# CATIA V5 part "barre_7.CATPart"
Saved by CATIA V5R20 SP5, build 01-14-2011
Part number: barre_7
Bounding box of the stored display mesh (mm): x 6 to 18, y -140.227 to 17.773, z 171.5 to 181.5
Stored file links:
  M:\EU_thinkMotion\IAO_2010\iao\IAO_MMS_Groupe2\IAO_MMS_Groupe2\sdubois\sdubois\sdubois\IAO_mecanisme\barre_7.CATPart
  M:\EU_thinkMotion\IAO_2010\iao\IAO_MMS_Groupe2\IAO_MMS_Groupe2\sdubois\sdubois\sdubois\IAO_mecanisme\assembage final.CATProduct
  M:\EU_thinkMotion\IAO_2010\iao\IAO_MMS_Groupe2\IAO_MMS_Groupe2\sdubois\sdubois\sdubois\IAO_mecanisme\squelette_7.CATPart
  M:\EU_thinkMotion\IAO_2010\iao\IAO_MMS_Groupe2\IAO_MMS_Groupe2\sdubois\sdubois\sdubois\IAO_mecanisme\bati_0.CATPart
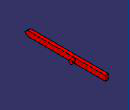
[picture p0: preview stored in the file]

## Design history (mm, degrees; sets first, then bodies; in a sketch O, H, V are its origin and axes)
External parameters (linked from other documents)
  External.largeur_barre_7 = 6 mm
  `External.diamètre trou oblong 'm'` = 8 mm
Set1
  Plane1 to Plane4: linked copy from another document
  Point1 to Point4: linked copy from another document
  DatumSurface1: linked copy from another document
Set2
  Point5: type Center, Curve edge [face of Pad2 from Sketch2.A1 | end face of Pad2]
Body1 (main body)
  Sketch1 on Plane1, origin (12, 0, 0), H (0, 1, 0), V (0, 0, 1)
    line L1 (-134.2269, 181.5) -> (17.7731, 181.5)
    point P1 (-134.2269, 181.5)
    point P2 (17.7731, 181.5)
    line L2 (-134.2269, 171.5) -> (17.7731, 171.5)
    point P3 (-134.2269, 171.5)
    point P4 (17.7731, 171.5)
    line L3 (-134.2269, 181.5) -> (-140.2269, 176.5)
    point P5 (-134.2269, 181.5)
    point P6 (-140.2269, 176.5)
    line L4 (-140.2269, 176.5) -> (-134.2269, 171.5)
    point P7 (-140.2269, 176.5)
    point P8 (-134.2269, 171.5)
    line L5 (17.7731, 181.5) -> (17.7731, 171.5)
    point P9 (17.7731, 181.5)
    point P10 (17.7731, 171.5)
    reference intersected line E1 through (0, 171.5) direction (-1, 0) from Plane2
    reference intersected line E2 through (0, 171.5) direction (-1, 0) from Plane2
    reference intersected line E3 through (17.7731, 0) direction (0, 1) from Plane3
    reference intersected line E4 through (-134.2269, 0) direction (0, 1) from Plane4
    reference projected point E5 (-44.2269, 181.5) from Point1
    reference intersected line E6 through (17.7731, 0) direction (0, 1) from Plane3
    reference intersected line E7 through (-134.2269, 0) direction (0, 1) from Plane4
    reference projected point E8 (-44.2269, 171.5) from Point2
    reference projected point E9 (-140.2269, 176.5) from Point3
    reference projected point E10 (-140.2269, 176.5) from Point3
    distance P2 E3 = 0
    distance P1 E4 = 0
    distance L1 E5 = 0
    distance P4 E6 = 0
    distance P3 E7 = 0
    distance L2 E8 = 0
    distance P9 P2 = 0
    distance P10 P4 = 0
    distance P8 P3 = 0
    distance P5 P1 = 0
    distance P7 E9 = 0
    distance P6 E10 = 0
    parallelism: L1 E1, L2 E2
  Sketch2 on Plane1, origin (12, 0, 0), H (0, 1, 0), V (0, 0, 1)
    circle A1 centre (-44.2269, 176.5) radius 4
    point P1 (-44.2269, 176.5)
    reference projected point E1 (-44.2269, 176.5) from Point4
    distance P1 E1 = 0
    radius A1 = 4 {= `External.diamètre trou oblong 'm'` /2}
  Pad1: profile Sketch1, direction (1, 0, 0), length 0 {= 2*External.largeur_barre_7 -12mm}, opposite side length 6 {= 12mm-External.largeur_barre_7}
  Pad2: profile Sketch2, direction (1, 0, 0), length 6 {= 3*External.largeur_barre_7 -12mm}, opposite side length 6 {= 12mm-External.largeur_barre_7}
Relations
  Pad1.FirstLimit.Length = 2*`Paramètres externes\largeur_barre` -6mm (deactivated)
  Pad2.FirstLimit.Length = 2*`Paramètres externes\largeur_barre` -6mm (deactivated)
  Pad1.FirstLimit.Length = 2*`Paramètres externes\largeur_barre` -6mm (deactivated)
